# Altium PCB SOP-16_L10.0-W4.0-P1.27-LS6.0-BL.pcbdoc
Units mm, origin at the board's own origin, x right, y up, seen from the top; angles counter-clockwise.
Board outline 23.1 x 20.19 mm, 2 copper layers (Top Layer, Bottom Layer), stack 0 mm thick; 1 components, 0 nets, 16 pads, 0 vias.
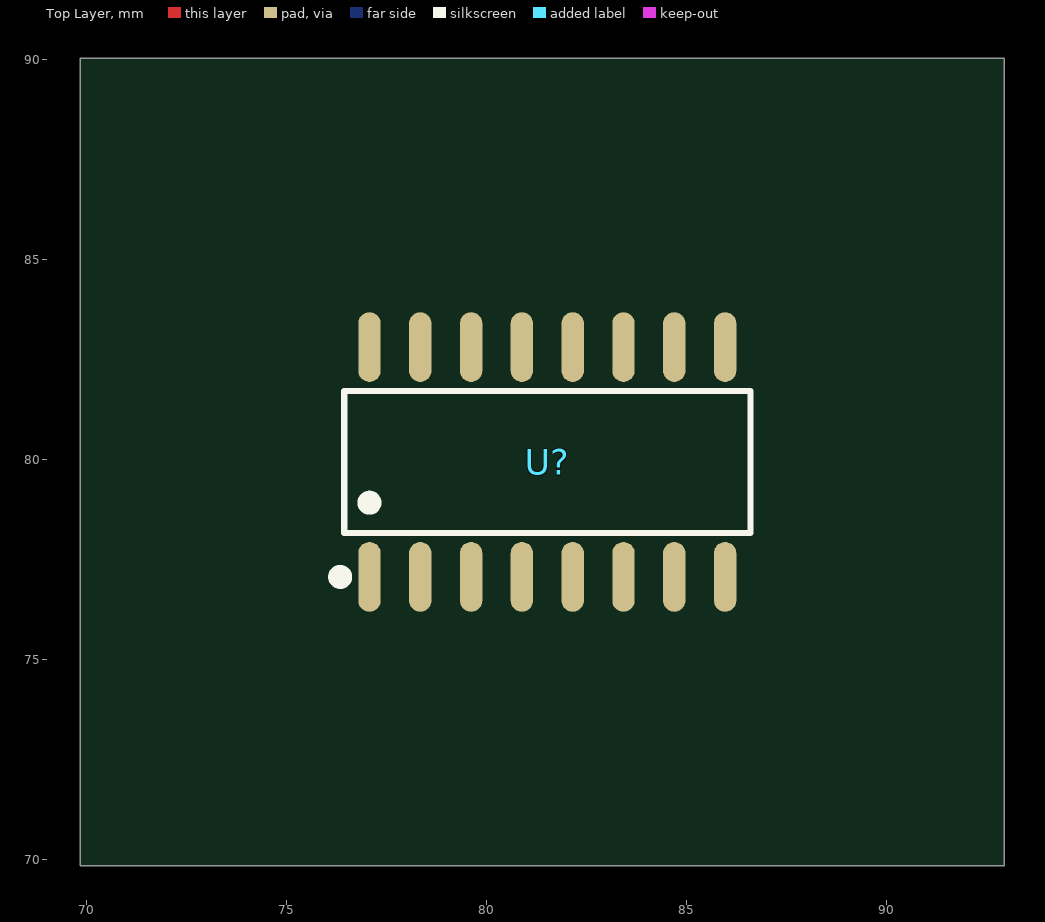
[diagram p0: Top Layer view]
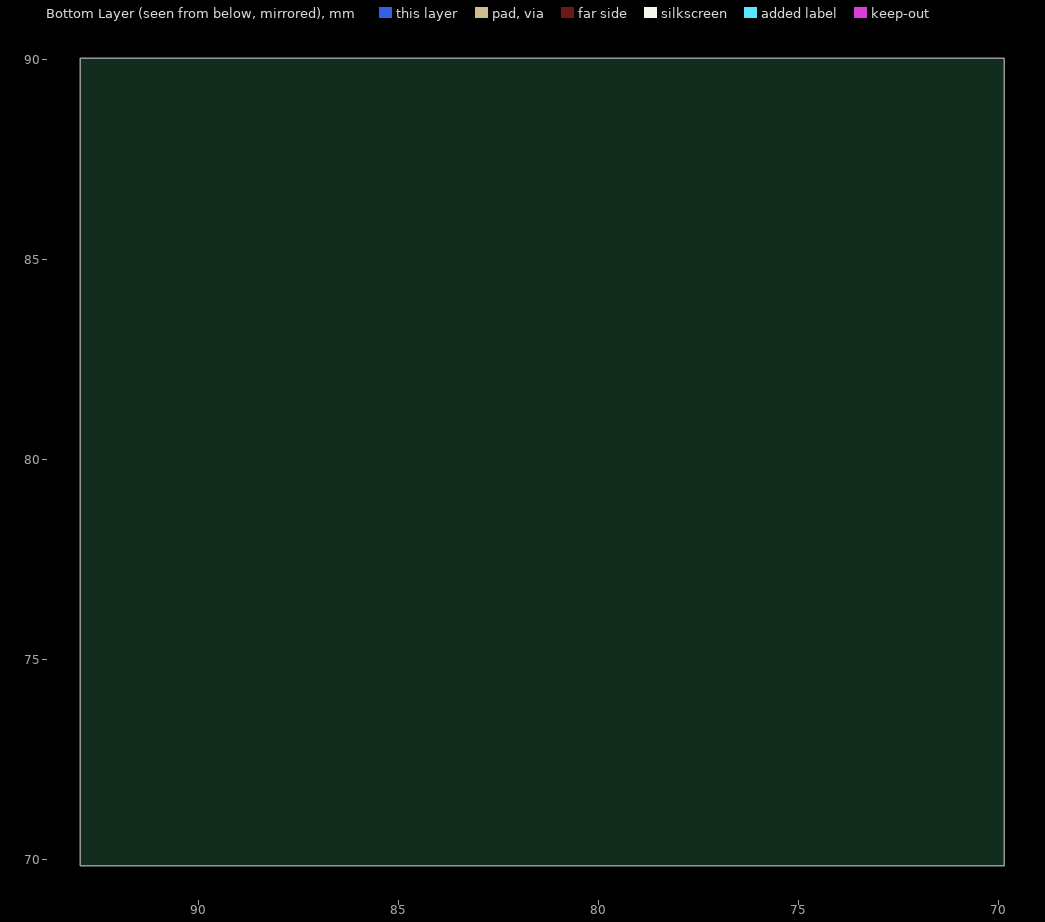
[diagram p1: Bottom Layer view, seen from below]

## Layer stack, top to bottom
Top Layer: signal copper (thickness not stored)
Bottom Layer: signal copper (thickness not stored)

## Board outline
92.954,69.85 69.85,69.85 69.85,90.04 92.954,90.04

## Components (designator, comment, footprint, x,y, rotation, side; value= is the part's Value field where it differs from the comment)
U? "" SOP-16_L10.0-W4.0-P1.27-LS6.0-BL 81.527,79.945 r0 top

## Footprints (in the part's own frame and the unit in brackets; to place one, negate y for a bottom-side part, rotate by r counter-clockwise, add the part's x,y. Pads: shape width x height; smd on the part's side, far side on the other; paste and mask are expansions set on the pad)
SOP-16_L10.0-W4.0-P1.27-LS6.0-BL [mm]
  oval 0.56x1.745 smd: 1(-4.445,-2.872) 2(-3.175,-2.872) 3(-1.905,-2.872) 4(-0.635,-2.872) 5(0.635,-2.872) 6(1.905,-2.872) 7(3.175,-2.872) 8(4.445,-2.872) 9(4.445,2.872) 10(3.175,2.872) 11(1.905,2.872) 12(0.635,2.872) 13(-0.635,2.872) 14(-1.905,2.872) 15(-3.175,2.872) 16(-4.445,2.872)
  silkscreen extent -5.33,-3.02 5.08,1.77

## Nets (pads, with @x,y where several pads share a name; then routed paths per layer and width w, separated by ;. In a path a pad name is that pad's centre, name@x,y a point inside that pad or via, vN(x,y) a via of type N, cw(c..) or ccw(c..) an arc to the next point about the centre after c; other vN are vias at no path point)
pads on no net: U?.1 U?.2 U?.3 U?.4 U?.5 U?.6 U?.7 U?.8 U?.9 U?.10 U?.11 U?.12 U?.13 U?.14 U?.15 U?.16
